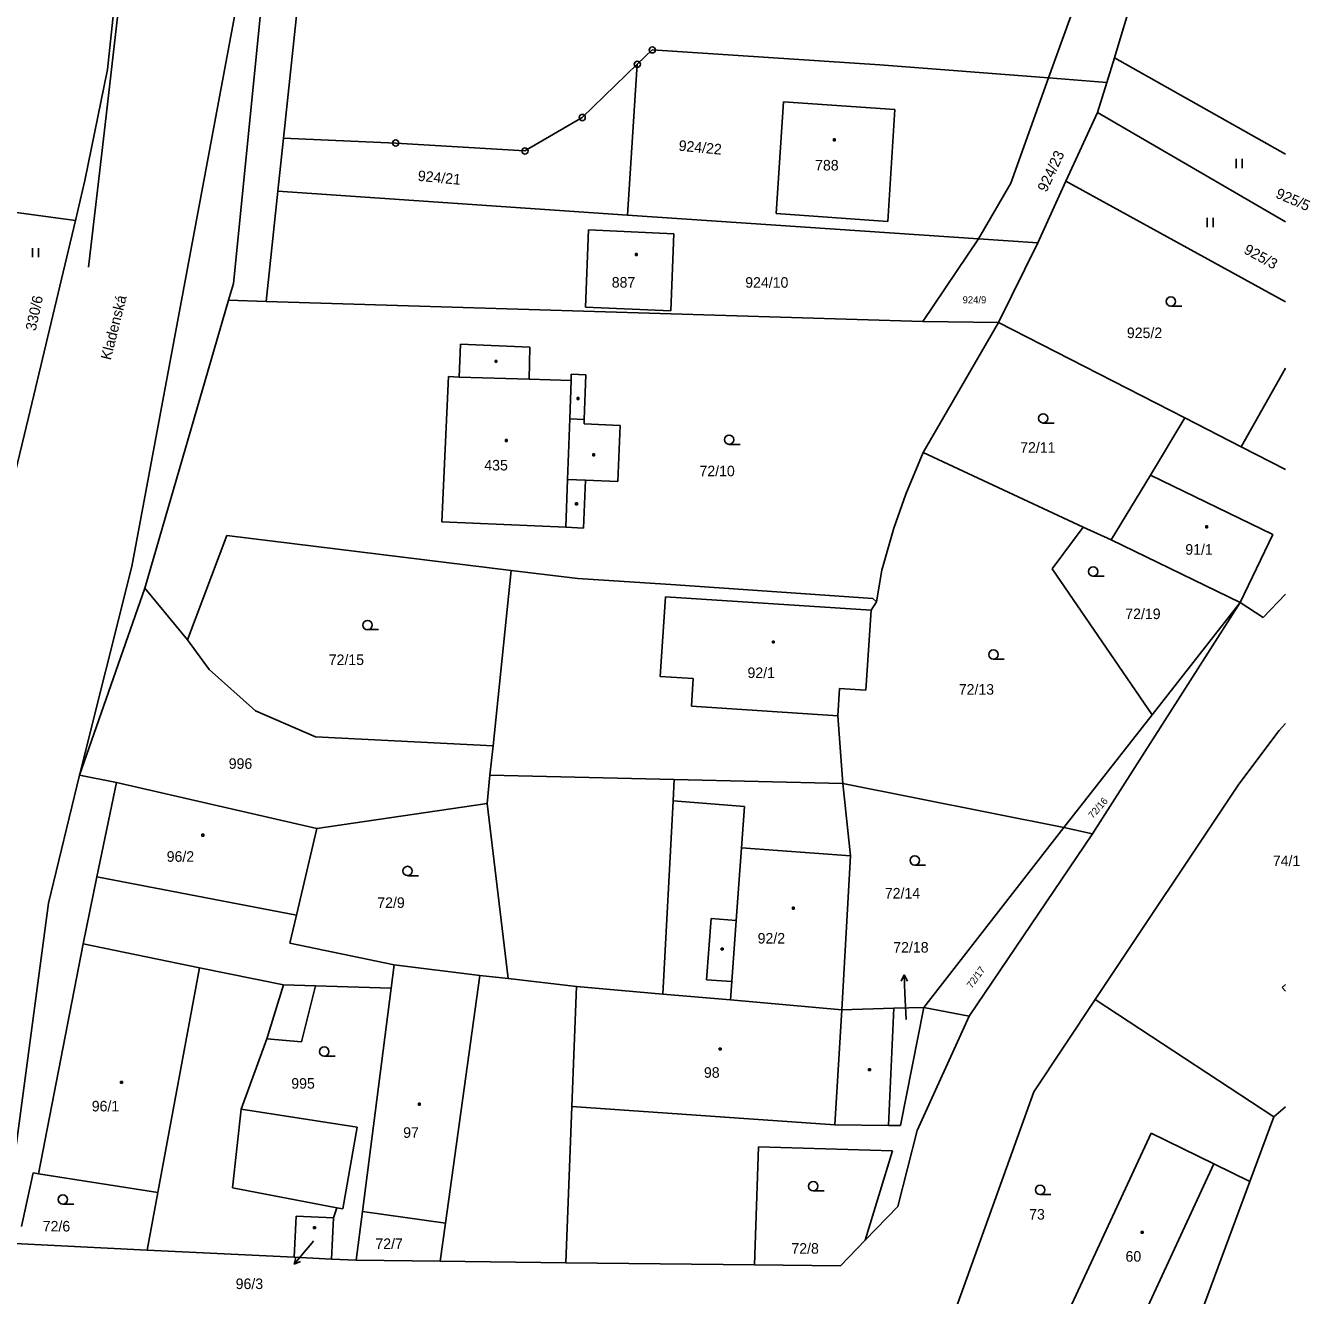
# Model space of a CAD drawing. Extents: x -770973 to -770265, y -1049936 to -1049427.
# Drawn here: x -770531.6 to -770428.1, y -1049834.2 to -1049731.9 of the extents above; entities that cross this region are included whole.
import ezdxf

# ---------------------------------------------------------------- set-up
doc = ezdxf.new("R2010")
doc.units = 0
for name, color, linetype in [('Vrstva 1', 7, 'Continuous'), ('Vrstva 13', 7, 'Continuous'), ('Vrstva 14', 7, 'Continuous'), ('Vrstva 15', 7, 'Continuous'), ('Vrstva 16', 7, 'Continuous'), ('Vrstva 2', 7, 'Continuous'), ('Vrstva 23', 7, 'Continuous'), ('Vrstva 25', 7, 'Continuous'), ('Vrstva 28', 7, 'Continuous'), ('Vrstva 38', 7, 'Continuous'), ('Vrstva 50', 7, 'Continuous')]:
    doc.layers.add(name, color=color, linetype=linetype)

msp = doc.modelspace()

# ---------------------------------------------------------------- linework, layer by layer
at = {"layer": 'Vrstva 1'}
for p, q in [((-770443.79, -1049734.32), (-770436, -1049708.43)), ((-770512.65, -1049719.7), (-770523.05, -1049775.51)), ((-770449.16, -1049736.12), (-770443.45, -1049720.22)), ((-770511.76, -1049721.8), (-770514.86, -1049752.7)), ((-770510.82, -1049740.97), (-770508.95, -1049723.22)), ((-770523.73, -1049723.36), (-770525, -1049735.43)), ((-770482.31, -1049735.02), (-770481.11, -1049733.86)), ((-770481.11, -1049733.86), (-770462.75, -1049735.07)), ((-770444.47, -1049736.48), (-770443.85, -1049734.51)), ((-770443.79, -1049734.32), (-770443.85, -1049734.51)), ((-770443.85, -1049734.51), (-770430.07, -1049742.27)), ((-770526.84, -1049744.38), (-770525, -1049735.43)), ((-770486.75, -1049739.31), (-770482.31, -1049735.02)), ((-770482.31, -1049735.02), (-770483.1, -1049747.18)), ((-770462.75, -1049735.07), (-770449.16, -1049736.12)), ((-770452.2, -1049744.59), (-770449.16, -1049736.12)), ((-770449.16, -1049736.12), (-770444.47, -1049736.48)), ((-770444.47, -1049736.48), (-770445.23, -1049738.9)), ((-770471.13, -1049747.05), (-770470.52, -1049738.05)), ((-770461.56, -1049738.67), (-770470.52, -1049738.05)), ((-770462.13, -1049747.69), (-770461.56, -1049738.67)), ((-770491.37, -1049742.01), (-770486.75, -1049739.31)), ((-770445.23, -1049738.9), (-770447.76, -1049744.45)), ((-770445.23, -1049738.9), (-770430.07, -1049747.72)), ((-770511.27, -1049745.26), (-770510.82, -1049740.97)), ((-770510.82, -1049740.97), (-770501.78, -1049741.37)), ((-770501.78, -1049741.37), (-770491.37, -1049742.01)), ((-770527.6, -1049747.6), (-770526.84, -1049744.38)), ((-770452.2, -1049744.59), (-770454.81, -1049749.1)), ((-770447.76, -1049744.45), (-770450.03, -1049749.42)), ((-770430.07, -1049754.17), (-770447.76, -1049744.45)), ((-770512.22, -1049754.13), (-770511.27, -1049745.26)), ((-770511.27, -1049745.26), (-770483.1, -1049747.18)), ((-770527.6, -1049747.6), (-770533.16, -1049746.85)), ((-770462.13, -1049747.69), (-770471.13, -1049747.05)), ((-770531.39, -1049763.49), (-770527.6, -1049747.6)), ((-770483.1, -1049747.18), (-770454.81, -1049749.1)), ((-770486.48, -1049754.59), (-770486.24, -1049748.37)), ((-770486.24, -1049748.37), (-770479.36, -1049748.68)), ((-770479.36, -1049748.68), (-770479.61, -1049754.9)), ((-770454.81, -1049749.1), (-770459.3, -1049755.76)), ((-770454.81, -1049749.1), (-770450.03, -1049749.42)), ((-770450.03, -1049749.42), (-770453.21, -1049755.82)), ((-770514.86, -1049752.7), (-770515.25, -1049754.04)), ((-770515.25, -1049754.04), (-770522.01, -1049777.25)), ((-770512.22, -1049754.13), (-770515.25, -1049754.04)), ((-770459.3, -1049755.76), (-770512.22, -1049754.13)), ((-770479.61, -1049754.9), (-770486.48, -1049754.59)), ((-770453.21, -1049755.82), (-770459.3, -1049755.76)), ((-770453.21, -1049755.82), (-770459.28, -1049766.32)), ((-770453.21, -1049755.82), (-770438.17, -1049763.53)), ((-770496.56, -1049757.58), (-770496.68, -1049760.23)), ((-770490.98, -1049757.82), (-770496.56, -1049757.58)), ((-770491.02, -1049760.4), (-770490.98, -1049757.82)), ((-770430.07, -1049759.51), (-770433.64, -1049765.86)), ((-770497.53, -1049760.19), (-770498.07, -1049771.89)), ((-770496.68, -1049760.23), (-770497.53, -1049760.19)), ((-770487.65, -1049760.5), (-770491.02, -1049760.4)), ((-770487.65, -1049760.5), (-770487.64, -1049760)), ((-770487.64, -1049760), (-770486.46, -1049760.05)), ((-770486.46, -1049760.05), (-770486.58, -1049763.66)), ((-770532.79, -1049769.4), (-770531.39, -1049763.49)), ((-770486.58, -1049763.66), (-770486.6, -1049764.01)), ((-770440.96, -1049768.14), (-770438.17, -1049763.53)), ((-770438.17, -1049763.53), (-770433.64, -1049765.86)), ((-770486.6, -1049764.01), (-770483.69, -1049764.14)), ((-770483.69, -1049764.14), (-770483.87, -1049768.64)), ((-770459.28, -1049766.32), (-770460.66, -1049769.68)), ((-770459.28, -1049766.32), (-770446.37, -1049772.32)), ((-770433.64, -1049765.86), (-770430.07, -1049767.69)), ((-770486.48, -1049768.54), (-770486.66, -1049772.41)), ((-770483.87, -1049768.64), (-770486.48, -1049768.54)), ((-770444.13, -1049773.36), (-770440.96, -1049768.14)), ((-770460.66, -1049769.68), (-770461.64, -1049772.42)), ((-770498.07, -1049771.89), (-770488.06, -1049772.34)), ((-770486.66, -1049772.41), (-770488.06, -1049772.34)), ((-770461.64, -1049772.42), (-770462.61, -1049775.79)), ((-770446.37, -1049772.32), (-770448.87, -1049775.69)), ((-770444.13, -1049773.36), (-770446.37, -1049772.32)), ((-770515.38, -1049773.01), (-770518.56, -1049781.42)), ((-770515.38, -1049773.01), (-770492.47, -1049775.82)), ((-770433.73, -1049778.4), (-770444.13, -1049773.36)), ((-770523.05, -1049775.51), (-770527.28, -1049792.32)), ((-770492.47, -1049775.82), (-770493.94, -1049789.95)), ((-770492.47, -1049775.82), (-770487.11, -1049776.48)), ((-770462.61, -1049775.79), (-770463.04, -1049778.36)), ((-770448.87, -1049775.69), (-770440.81, -1049787.45)), ((-770479.2, -1049776.97), (-770487.11, -1049776.48)), ((-770479.2, -1049776.97), (-770463.34, -1049778.07)), ((-770522.01, -1049777.25), (-770527.28, -1049792.32)), ((-770522.01, -1049777.25), (-770518.56, -1049781.42)), ((-770463.34, -1049778.07), (-770463.04, -1049778.36)), ((-770430.07, -1049777.74), (-770431.86, -1049779.62)), ((-770463.88, -1049785.48), (-770463.46, -1049779.02)), ((-770463.04, -1049778.36), (-770463.46, -1049779.02)), ((-770445.62, -1049797.04), (-770433.73, -1049778.4)), ((-770433.73, -1049778.4), (-770440.81, -1049787.45)), ((-770431.86, -1049779.62), (-770433.73, -1049778.4)), ((-770516.82, -1049783.81), (-770518.56, -1049781.42)), ((-770513.07, -1049787.14), (-770516.82, -1049783.81)), ((-770466.02, -1049785.34), (-770466.16, -1049787.54)), ((-770463.88, -1049785.48), (-770466.02, -1049785.34)), ((-770508.25, -1049789.23), (-770513.07, -1049787.14)), ((-770440.81, -1049787.45), (-770447.92, -1049796.55)), ((-770466.16, -1049787.54), (-770465.75, -1049792.98)), ((-770430.58, -1049788.71), (-770430.07, -1049788.16)), ((-770493.94, -1049789.95), (-770508.25, -1049789.23)), ((-770433.82, -1049793.04), (-770430.58, -1049788.71)), ((-770493.94, -1049789.95), (-770494.19, -1049792.32)), ((-770527.28, -1049792.32), (-770529.77, -1049802.63)), ((-770527.28, -1049792.32), (-770524.28, -1049792.9)), ((-770494.19, -1049792.32), (-770494.4, -1049794.61)), ((-770494.19, -1049792.32), (-770479.33, -1049792.66)), ((-770479.33, -1049792.66), (-770465.75, -1049792.98)), ((-770525.86, -1049800.52), (-770524.28, -1049792.9)), ((-770524.28, -1049792.9), (-770508.15, -1049796.62)), ((-770465.75, -1049792.98), (-770465.14, -1049798.81)), ((-770447.92, -1049796.55), (-770465.75, -1049792.98)), ((-770445.41, -1049810.41), (-770433.82, -1049793.04)), ((-770494.4, -1049794.61), (-770508.15, -1049796.62)), ((-770494.4, -1049794.61), (-770492.73, -1049808.72)), ((-770508.15, -1049796.62), (-770509.79, -1049803.61)), ((-770459.23, -1049811.04), (-770447.92, -1049796.55)), ((-770447.92, -1049796.55), (-770445.62, -1049797.04)), ((-770445.62, -1049797.04), (-770455.56, -1049811.75)), ((-770465.14, -1049798.81), (-770465.82, -1049811.24)), ((-770525.86, -1049800.52), (-770526.98, -1049805.92)), ((-770529.77, -1049802.63), (-770532.71, -1049824.8)), ((-770509.79, -1049803.61), (-770510.32, -1049805.85)), ((-770526.98, -1049805.92), (-770517.6, -1049807.84)), ((-770510.32, -1049805.85), (-770501.91, -1049807.6)), ((-770517.6, -1049807.84), (-770510.83, -1049809.22)), ((-770501.91, -1049807.6), (-770502.15, -1049809.48)), ((-770501.91, -1049807.6), (-770494.99, -1049808.46)), ((-770510.83, -1049809.22), (-770508.26, -1049809.3)), ((-770494.99, -1049808.46), (-770492.73, -1049808.72)), ((-770492.73, -1049808.72), (-770487.21, -1049809.34)), ((-770430.33, -1049809.43), (-770430.07, -1049809.19)), ((-770509.38, -1049813.8), (-770508.26, -1049809.3)), ((-770508.26, -1049809.3), (-770502.15, -1049809.48)), ((-770502.15, -1049809.48), (-770504.47, -1049827.48)), ((-770487.21, -1049809.34), (-770487.58, -1049819.03)), ((-770487.21, -1049809.34), (-770480.24, -1049809.96)), ((-770480.24, -1049809.96), (-770474.8, -1049810.44)), ((-770430.33, -1049809.43), (-770430.07, -1049809.72)), ((-770474.8, -1049810.44), (-770465.82, -1049811.24)), ((-770465.82, -1049811.24), (-770461.63, -1049811.11)), ((-770461.63, -1049811.11), (-770462.07, -1049820.55)), ((-770461.63, -1049811.11), (-770459.23, -1049811.04)), ((-770459.23, -1049811.04), (-770461.11, -1049820.56)), ((-770455.56, -1049811.75), (-770459.23, -1049811.04)), ((-770450.36, -1049817.83), (-770445.41, -1049810.41)), ((-770431, -1049819.86), (-770445.41, -1049810.41)), ((-770455.56, -1049811.75), (-770459.76, -1049820.96)), ((-770514.23, -1049819.23), (-770512.18, -1049813.58)), ((-770512.18, -1049813.58), (-770509.38, -1049813.8)), ((-770458.29, -1049839.9), (-770450.36, -1049817.83)), ((-770514.23, -1049819.23), (-770504.9, -1049820.69)), ((-770487.58, -1049819.03), (-770488.07, -1049831.62)), ((-770430.07, -1049819.05), (-770431, -1049819.86)), ((-770461.11, -1049820.56), (-770462.07, -1049820.55)), ((-770432.93, -1049825.06), (-770431, -1049819.86)), ((-770504.9, -1049820.69), (-770506.05, -1049827.27)), ((-770459.76, -1049820.96), (-770461.3, -1049827.08)), ((-770440.9, -1049821.18), (-770447.63, -1049835.71)), ((-770435.83, -1049823.65), (-770440.9, -1049821.18)), ((-770472.55, -1049822.27), (-770472.87, -1049831.79)), ((-770472.55, -1049822.27), (-770461.74, -1049822.61)), ((-770461.74, -1049822.61), (-770463.94, -1049829.81)), ((-770435.83, -1049823.65), (-770432.93, -1049825.06)), ((-770531, -1049824.37), (-770531.95, -1049828.71)), ((-770530.58, -1049824.44), (-770531, -1049824.37)), ((-770530.58, -1049824.44), (-770520.95, -1049825.95)), ((-770438.2, -1049839.27), (-770432.93, -1049825.06)), ((-770520.95, -1049825.95), (-770521.81, -1049830.6)), ((-770509.96, -1049831.17), (-770509.8, -1049827.86)), ((-770509.8, -1049827.86), (-770506.79, -1049828.01)), ((-770506.79, -1049828.01), (-770506.53, -1049827.18)), ((-770506.05, -1049827.27), (-770506.53, -1049827.18)), ((-770504.47, -1049827.48), (-770504.98, -1049831.42)), ((-770504.47, -1049827.48), (-770497.78, -1049828.44)), ((-770461.3, -1049827.08), (-770463.94, -1049829.81)), ((-770506.79, -1049828.01), (-770506.95, -1049831.32)), ((-770497.78, -1049828.44), (-770498.21, -1049831.5)), ((-770463.94, -1049829.81), (-770465.94, -1049831.87)), ((-770521.81, -1049830.6), (-770533.02, -1049830.05)), ((-770509.96, -1049831.17), (-770521.81, -1049830.6)), ((-770506.95, -1049831.32), (-770509.96, -1049831.17)), ((-770504.98, -1049831.42), (-770506.95, -1049831.32)), ((-770498.21, -1049831.5), (-770504.98, -1049831.42)), ((-770488.07, -1049831.62), (-770498.21, -1049831.5)), ((-770472.87, -1049831.79), (-770488.07, -1049831.62)), ((-770465.94, -1049831.87), (-770472.87, -1049831.79))]:
    msp.add_line(p, q, dxfattribs=at)
at = {"layer": 'Vrstva 13'}
for p, q in [((-770460.64, -1049812.02), (-770460.74, -1049809.92)), ((-770508.41, -1049829.87), (-770509, -1049830.58))]:
    msp.add_line(p, q, dxfattribs=at)
at = {"layer": 'Vrstva 16'}
for p, q in [((-770460.81, -1049808.42), (-770461.04, -1049808.93)), ((-770460.74, -1049809.92), (-770460.81, -1049808.42)), ((-770460.81, -1049808.42), (-770460.54, -1049808.91)), ((-770509, -1049830.58), (-770509.96, -1049831.74)), ((-770509.96, -1049831.74), (-770509.83, -1049831.19)), ((-770509.96, -1049831.74), (-770509.45, -1049831.51))]:
    msp.add_line(p, q, dxfattribs=at)
at = {"layer": 'Vrstva 2'}
for p, q in [((-770496.68, -1049760.23), (-770491.02, -1049760.4)), ((-770487.65, -1049760.5), (-770487.76, -1049763.6)), ((-770487.76, -1049763.6), (-770487.93, -1049768.48)), ((-770487.76, -1049763.6), (-770486.58, -1049763.66)), ((-770487.93, -1049768.48), (-770488.06, -1049772.34)), ((-770487.93, -1049768.48), (-770486.48, -1049768.54)), ((-770431.08, -1049772.91), (-770440.96, -1049768.14)), ((-770433.73, -1049778.4), (-770431.08, -1049772.91)), ((-770480.04, -1049777.94), (-770480.47, -1049784.36)), ((-770480.04, -1049777.94), (-770463.46, -1049779.02)), ((-770477.81, -1049784.54), (-770480.47, -1049784.36)), ((-770477.81, -1049784.54), (-770477.95, -1049786.77)), ((-770466.16, -1049787.54), (-770477.95, -1049786.77)), ((-770479.33, -1049792.66), (-770479.42, -1049794.4)), ((-770479.42, -1049794.4), (-770480.24, -1049809.96)), ((-770479.42, -1049794.4), (-770473.67, -1049794.84)), ((-770473.67, -1049794.84), (-770473.91, -1049798.18)), ((-770473.91, -1049798.18), (-770474.33, -1049804.03)), ((-770465.14, -1049798.81), (-770473.91, -1049798.18)), ((-770525.86, -1049800.52), (-770509.79, -1049803.61)), ((-770476.72, -1049808.81), (-770476.36, -1049803.88)), ((-770476.36, -1049803.88), (-770474.33, -1049804.03)), ((-770474.33, -1049804.03), (-770474.69, -1049808.96)), ((-770526.98, -1049805.92), (-770530.58, -1049824.44)), ((-770517.6, -1049807.84), (-770520.95, -1049825.95)), ((-770512.18, -1049813.58), (-770510.83, -1049809.22)), ((-770494.99, -1049808.46), (-770497.78, -1049828.44)), ((-770476.72, -1049808.81), (-770474.69, -1049808.96)), ((-770474.69, -1049808.96), (-770474.8, -1049810.44)), ((-770466.39, -1049820.49), (-770465.82, -1049811.24)), ((-770514.94, -1049825.58), (-770514.23, -1049819.23)), ((-770466.39, -1049820.49), (-770487.58, -1049819.03)), ((-770462.07, -1049820.55), (-770466.39, -1049820.49)), ((-770435.83, -1049823.65), (-770442.52, -1049838.08)), ((-770506.53, -1049827.18), (-770514.94, -1049825.58))]:
    msp.add_line(p, q, dxfattribs=at)
at = {"layer": 'Vrstva 23'}
for p, q in [((-770434.05, -1049743.39), (-770434.05, -1049742.64)), ((-770433.55, -1049742.64), (-770433.55, -1049743.39)), ((-770436.39, -1049748.16), (-770436.39, -1049747.41)), ((-770435.89, -1049747.41), (-770435.89, -1049748.16)), ((-770531.06, -1049750.58), (-770531.06, -1049749.83)), ((-770530.56, -1049749.83), (-770530.56, -1049750.58)), ((-770439.3, -1049754.51), (-770438.42, -1049754.51)), ((-770449.6, -1049763.94), (-770448.72, -1049763.94)), ((-770474.91, -1049765.66), (-770474.03, -1049765.66)), ((-770445.57, -1049776.28), (-770444.69, -1049776.28)), ((-770504.05, -1049780.59), (-770503.17, -1049780.59)), ((-770453.61, -1049782.98), (-770452.73, -1049782.98)), ((-770459.95, -1049799.56), (-770459.07, -1049799.56)), ((-770500.83, -1049800.42), (-770499.95, -1049800.42)), ((-770507.54, -1049814.98), (-770506.66, -1049814.98)), ((-770468.13, -1049825.82), (-770467.25, -1049825.82)), ((-770449.85, -1049826.12), (-770448.97, -1049826.12)), ((-770528.61, -1049826.9), (-770527.73, -1049826.9))]:
    msp.add_line(p, q, dxfattribs=at)
for centre in [(-770439.3, -1049754.14), (-770449.6, -1049763.56), (-770474.91, -1049765.28), (-770445.57, -1049775.91), (-770504.05, -1049780.22), (-770453.61, -1049782.6), (-770459.95, -1049799.19), (-770500.83, -1049800.04), (-770507.54, -1049814.6), (-770468.13, -1049825.45), (-770449.85, -1049825.75), (-770528.61, -1049826.52)]:
    msp.add_circle(centre, 0.375, dxfattribs=at)
at = {"layer": 'Vrstva 25'}
for p, q in [((-770466.51, -1049741.04), (-770466.36, -1049741.04)), ((-770466.51, -1049741.19), (-770466.51, -1049741.04)), ((-770466.36, -1049741.19), (-770466.51, -1049741.19)), ((-770466.36, -1049741.04), (-770466.36, -1049741.19)), ((-770482.46, -1049750.28), (-770482.31, -1049750.28)), ((-770482.46, -1049750.43), (-770482.46, -1049750.28)), ((-770482.31, -1049750.43), (-770482.46, -1049750.43)), ((-770482.31, -1049750.28), (-770482.31, -1049750.43)), ((-770493.77, -1049758.89), (-770493.62, -1049758.89)), ((-770493.77, -1049759.04), (-770493.77, -1049758.89)), ((-770493.62, -1049759.04), (-770493.77, -1049759.04)), ((-770493.62, -1049758.89), (-770493.62, -1049759.04)), ((-770487.17, -1049761.89), (-770487.02, -1049761.89)), ((-770487.17, -1049762.04), (-770487.17, -1049761.89)), ((-770487.02, -1049762.04), (-770487.17, -1049762.04)), ((-770487.02, -1049761.89), (-770487.02, -1049762.04)), ((-770492.94, -1049765.27), (-770492.79, -1049765.27)), ((-770492.94, -1049765.42), (-770492.94, -1049765.27)), ((-770492.79, -1049765.42), (-770492.94, -1049765.42)), ((-770492.79, -1049765.27), (-770492.79, -1049765.42)), ((-770485.9, -1049766.43), (-770485.75, -1049766.43)), ((-770485.9, -1049766.58), (-770485.9, -1049766.43)), ((-770485.75, -1049766.58), (-770485.9, -1049766.58)), ((-770485.75, -1049766.43), (-770485.75, -1049766.58)), ((-770487.28, -1049770.37), (-770487.13, -1049770.37)), ((-770487.28, -1049770.52), (-770487.28, -1049770.37)), ((-770487.13, -1049770.52), (-770487.28, -1049770.52)), ((-770487.13, -1049770.37), (-770487.13, -1049770.52)), ((-770436.5, -1049772.23), (-770436.35, -1049772.23)), ((-770436.5, -1049772.38), (-770436.5, -1049772.23)), ((-770436.35, -1049772.38), (-770436.5, -1049772.38)), ((-770436.35, -1049772.23), (-770436.35, -1049772.38)), ((-770471.42, -1049781.51), (-770471.27, -1049781.51)), ((-770471.42, -1049781.66), (-770471.42, -1049781.51)), ((-770471.27, -1049781.66), (-770471.42, -1049781.66)), ((-770471.27, -1049781.51), (-770471.27, -1049781.66)), ((-770517.41, -1049797.08), (-770517.26, -1049797.08)), ((-770517.41, -1049797.23), (-770517.41, -1049797.08)), ((-770517.26, -1049797.23), (-770517.41, -1049797.23)), ((-770517.26, -1049797.08), (-770517.26, -1049797.23)), ((-770469.81, -1049802.96), (-770469.66, -1049802.96)), ((-770469.81, -1049803.11), (-770469.81, -1049802.96)), ((-770469.66, -1049802.96), (-770469.66, -1049803.11)), ((-770469.66, -1049803.11), (-770469.81, -1049803.11)), ((-770475.55, -1049806.26), (-770475.4, -1049806.26)), ((-770475.55, -1049806.41), (-770475.55, -1049806.26)), ((-770475.4, -1049806.41), (-770475.55, -1049806.41)), ((-770475.4, -1049806.26), (-770475.4, -1049806.41)), ((-770475.7, -1049814.32), (-770475.55, -1049814.32)), ((-770475.7, -1049814.47), (-770475.7, -1049814.32)), ((-770475.55, -1049814.32), (-770475.55, -1049814.47)), ((-770475.55, -1049814.47), (-770475.7, -1049814.47)), ((-770463.67, -1049815.98), (-770463.52, -1049815.98)), ((-770463.67, -1049816.13), (-770463.67, -1049815.98)), ((-770463.52, -1049816.13), (-770463.67, -1049816.13)), ((-770463.52, -1049815.98), (-770463.52, -1049816.13)), ((-770523.96, -1049817), (-770523.81, -1049817)), ((-770523.96, -1049817.15), (-770523.96, -1049817)), ((-770523.81, -1049817.15), (-770523.96, -1049817.15)), ((-770523.81, -1049817), (-770523.81, -1049817.15)), ((-770499.95, -1049818.76), (-770499.8, -1049818.76)), ((-770499.95, -1049818.91), (-770499.95, -1049818.76)), ((-770499.8, -1049818.91), (-770499.95, -1049818.91)), ((-770499.8, -1049818.76), (-770499.8, -1049818.91)), ((-770508.4, -1049828.72), (-770508.25, -1049828.72)), ((-770508.4, -1049828.87), (-770508.4, -1049828.72)), ((-770508.25, -1049828.87), (-770508.4, -1049828.87)), ((-770508.25, -1049828.72), (-770508.25, -1049828.87)), ((-770441.69, -1049829.09), (-770441.54, -1049829.09)), ((-770441.69, -1049829.24), (-770441.69, -1049829.09)), ((-770441.54, -1049829.24), (-770441.69, -1049829.24)), ((-770441.54, -1049829.09), (-770441.54, -1049829.24))]:
    msp.add_line(p, q, dxfattribs=at)
at = {"layer": 'Vrstva 28'}
for centre, radius in [((-770481.11, -1049733.86), 0.25), ((-770481.11, -1049733.86), 0.005), ((-770482.31, -1049735.02), 0.25), ((-770482.31, -1049735.02), 0.005), ((-770486.75, -1049739.31), 0.25), ((-770486.75, -1049739.31), 0.005), ((-770501.78, -1049741.37), 0.25), ((-770501.78, -1049741.37), 0.005), ((-770491.37, -1049742.01), 0.25), ((-770491.37, -1049742.01), 0.005)]:
    msp.add_circle(centre, radius, dxfattribs=at)
at = {"layer": 'Vrstva 50'}
for p, q in [((-770523.88, -1049728.37), (-770525.29, -1049740.56)), ((-770525.29, -1049740.56), (-770526.54, -1049751.37))]:
    msp.add_line(p, q, dxfattribs=at)

# ---------------------------------------------------------------- texts
at = {"layer": 'Vrstva 14'}
for s, height, rotation, p in [('924/22', 0.85, 354.5471, (-770479.01, -1049741.98)), ('924/23', 0.85, 64.9994, (-770449.33, -1049745.38)), ('924/21', 0.85, 354.5471, (-770500.03, -1049744.41)), ('925/5', 0.85, 336.5713, (-770430.93, -1049745.74)), ('925/3', 0.85, 331.2908, (-770433.5, -1049750.21)), ('330/6', 0.85, 77.7885, (-770530.8, -1049756.55)), ('72/16', 0.57, 49.1611, (-770445.59, -1049795.87)), ('72/17', 0.57, 54.1396, (-770455.35, -1049809.55))]:
    msp.add_text(s, height=height, rotation=rotation, dxfattribs=at).set_placement(p)
for s, height, p in [('924/10', 0.85, (-770473.61, -1049753.03)), ('924/9', 0.57, (-770456.09, -1049754.29)), ('925/2', 0.85, (-770442.85, -1049757.09)), ('72/11', 0.85, (-770451.45, -1049766.33)), ('72/10', 0.85, (-770477.3, -1049768.23)), ('72/19', 0.85, (-770442.98, -1049779.74)), ('72/15', 0.85, (-770507.18, -1049783.44)), ('72/13', 0.85, (-770456.4, -1049785.83)), ('996', 0.85, (-770515.24, -1049791.81)), ('74/1', 0.85, (-770431.09, -1049799.65)), ('72/14', 0.85, (-770462.36, -1049802.26)), ('72/9', 0.85, (-770503.27, -1049803.02)), ('72/18', 0.05, (-770460.74, -1049812.02)), ('995', 0.85, (-770510.2, -1049817.59)), ('73', 0.85, (-770450.73, -1049828.14)), ('72/6', 0.85, (-770530.23, -1049829.1)), ('72/7', 0.85, (-770503.42, -1049830.51)), ('72/8', 0.85, (-770469.89, -1049830.89))]:
    msp.add_text(s, height=height, dxfattribs=at).set_placement(p)
at = {"layer": 'Vrstva 15'}
for s, height, p in [('788', 0.85, (-770467.98, -1049743.58)), ('887', 0.85, (-770484.37, -1049753.02)), ('435', 0.85, (-770494.64, -1049767.76)), ('91/1', 0.85, (-770438.14, -1049774.55)), ('92/1', 0.85, (-770473.43, -1049784.49)), ('96/2', 0.85, (-770520.24, -1049799.3)), ('92/2', 0.85, (-770472.61, -1049805.89)), ('98', 0.85, (-770476.94, -1049816.71)), ('96/1', 0.85, (-770526.28, -1049819.42)), ('97', 0.85, (-770501.18, -1049821.55)), ('96/3', 0.05, (-770508.49, -1049829.87)), ('60', 0.85, (-770442.96, -1049831.53))]:
    msp.add_text(s, height=height, dxfattribs=at).set_placement(p)
at = {"layer": 'Vrstva 16'}
for s, p in [('72/18', (-770461.68, -1049806.62)), ('96/3', (-770514.68, -1049833.74))]:
    msp.add_text(s, height=0.85, dxfattribs=at).set_placement(p)
at = {"layer": 'Vrstva 38'}
msp.add_text('Kladenská', height=0.85, rotation=75.9638, dxfattribs=at).set_placement((-770524.75, -1049758.91))

doc.saveas('drawing.dxf')
